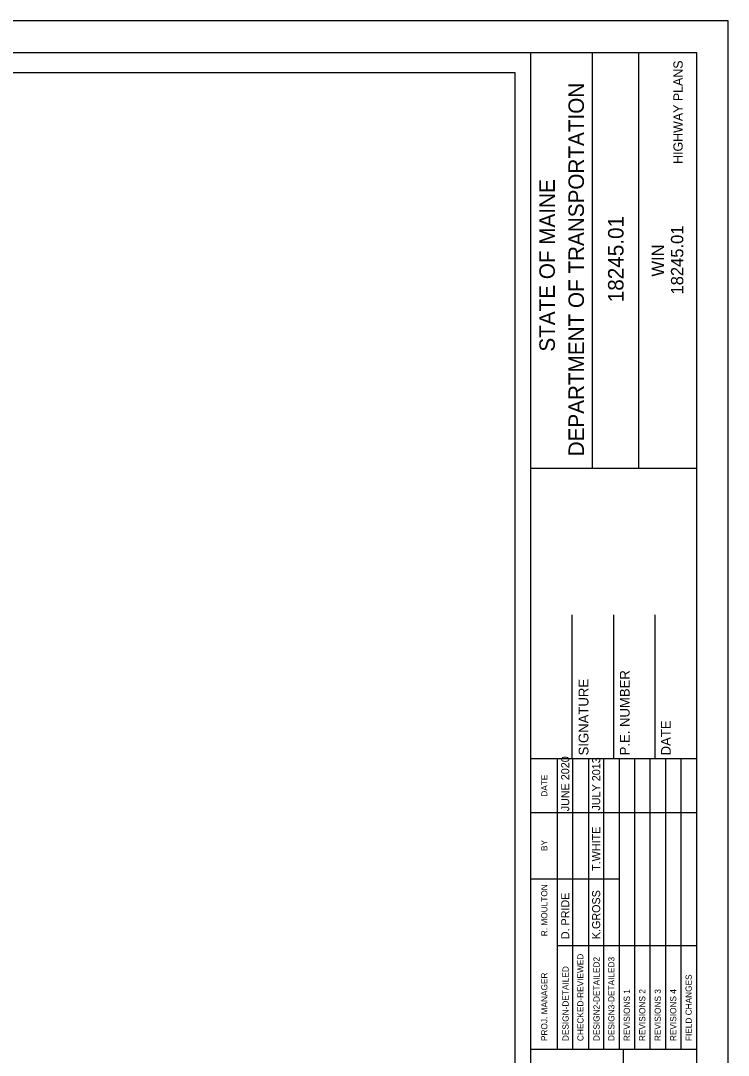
# Model space of a CAD drawing. Extents: x 1026502 to 1027102, y 781811 to 782040.
# Drawn here: x 1026720.77 to 1026754.88, y 781892.58 to 781942.42 of the extents above; entities that cross this region are included whole.
import ezdxf

# ---------------------------------------------------------------- set-up
doc = ezdxf.new("R2010")
doc.units = 0
for name, color, linetype in [('BORDER', 7, 'Continuous'), ('JUNK', 7, 'Continuous'), ('PLOT BOUNDARY', 7, 'Continuous')]:
    doc.layers.add(name, color=color, linetype=linetype)

msp = doc.modelspace()

# ---------------------------------------------------------------- linework, layer by layer
at = {"layer": 'BORDER'}
for p, q in [((1026753.357, 781940.868), (1026625.357, 781940.868)), ((1026745.357, 781856.871), (1026745.357, 781940.871)), ((1026748.34, 781920.866), (1026748.34, 781940.866)), ((1026750.576, 781920.866), (1026750.576, 781940.866)), ((1026753.357, 781856.871), (1026753.357, 781940.871)), ((1026745.358, 781920.863), (1026753.357, 781920.863)), ((1026747.357, 781906.871), (1026747.357, 781913.789)), ((1026749.357, 781906.871), (1026749.357, 781913.789)), ((1026751.357, 781906.871), (1026751.357, 781913.789)), ((1026745.357, 781906.871), (1026753.357, 781906.871)), ((1026745.357, 781892.871), (1026753.357, 781892.871)), ((1026749.83, 781864.871), (1026749.83, 781892.871))]:
    msp.add_line(p, q, dxfattribs=at)
for points in [[(1026746.649, 781904.271), (1026746.649, 781906.871)], [(1026747.395, 781892.873), (1026747.395, 781906.871)], [(1026748.14, 781906.871), (1026748.14, 781892.873)], [(1026748.886, 781892.873), (1026748.886, 781906.871)], [(1026749.631, 781892.873), (1026749.631, 781906.871)], [(1026750.376, 781892.873), (1026750.376, 781906.871)], [(1026751.122, 781892.873), (1026751.122, 781906.871)], [(1026751.867, 781892.873), (1026751.867, 781906.871)], [(1026752.612, 781892.873), (1026752.612, 781906.871)], [(1026746.65, 781892.873), (1026746.65, 781906.306)], [(1026745.357, 781904.271), (1026753.357, 781904.271)], [(1026745.357, 781901.071), (1026746.65, 781901.071)], [(1026746.649, 781901.071), (1026749.63, 781901.071)], [(1026746.649, 781897.871), (1026753.357, 781897.871)]]:
    msp.add_lwpolyline(points, dxfattribs=at)
at = {"layer": 'JUNK'}
msp.add_lwpolyline([(1026626.458, 781939.919), (1026744.596, 781939.919), (1026744.596, 781857.651), (1026626.458, 781857.651)], close=True, dxfattribs=at)
at = {"layer": 'PLOT BOUNDARY'}
msp.add_lwpolyline([(1026618.883, 781854.421), (1026754.882, 781854.421), (1026754.882, 781942.421), (1026618.883, 781942.421)], close=True, dxfattribs=at)

# ---------------------------------------------------------------- texts
at = {"layer": 'BORDER'}
for s, height, p in [('HIGHWAY PLANS', 0.44721, (1026752.684, 781935.52)), ('DEPARTMENT OF TRANSPORTATION', 0.7454, (1026747.923, 781921.433)), ('STATE OF MAINE', 0.7454, (1026746.521, 781926.478)), ('18245.01', 0.7454, (1026749.831, 781928.856)), ('18245.01', 0.5962, (1026752.714, 781929.228)), ('WIN', 0.5962, (1026751.786, 781930.092)), ('P.E. NUMBER', 0.47244, (1026750.126, 781907.024)), ('SIGNATURE', 0.4724, (1026748.141, 781907.024)), ('DATE', 0.4724, (1026752.11, 781907.024)), ('JUNE 2020', 0.3876, (1026747.215, 781904.331)), ('JULY 2013', 0.3876, (1026748.706, 781904.368)), ('DATE', 0.2971, (1026746.161, 781905.035)), ('T.WHITE', 0.3876, (1026748.706, 781901.459)), ('BY', 0.2971, (1026746.161, 781902.419)), ('R. MOULTON', 0.2982, (1026746.161, 781898.313)), ('D. PRIDE', 0.3876, (1026747.215, 781898.169)), ('K.GROSS', 0.3876, (1026748.706, 781898.169)), ('CHECKED-REVIEWED', 0.2982, (1026747.902, 781893.261)), ('DESIGN-DETAILED', 0.2982, (1026747.186, 781893.261)), ('DESIGN2-DETAILED2', 0.2982, (1026748.677, 781893.261)), ('DESIGN3-DETAILED3', 0.2982, (1026749.393, 781893.261)), ('PROJ. MANAGER', 0.2982, (1026746.161, 781893.261)), ('FIELD CHANGES', 0.2982, (1026753.119, 781893.261)), ('REVISIONS 1', 0.2982, (1026750.138, 781893.261)), ('REVISIONS 2', 0.2982, (1026750.883, 781893.261)), ('REVISIONS 3', 0.2982, (1026751.629, 781893.261)), ('REVISIONS 4', 0.2982, (1026752.374, 781893.261))]:
    msp.add_text(s, height=height, rotation=90, dxfattribs=at).set_placement(p)

doc.saveas('drawing.dxf')
